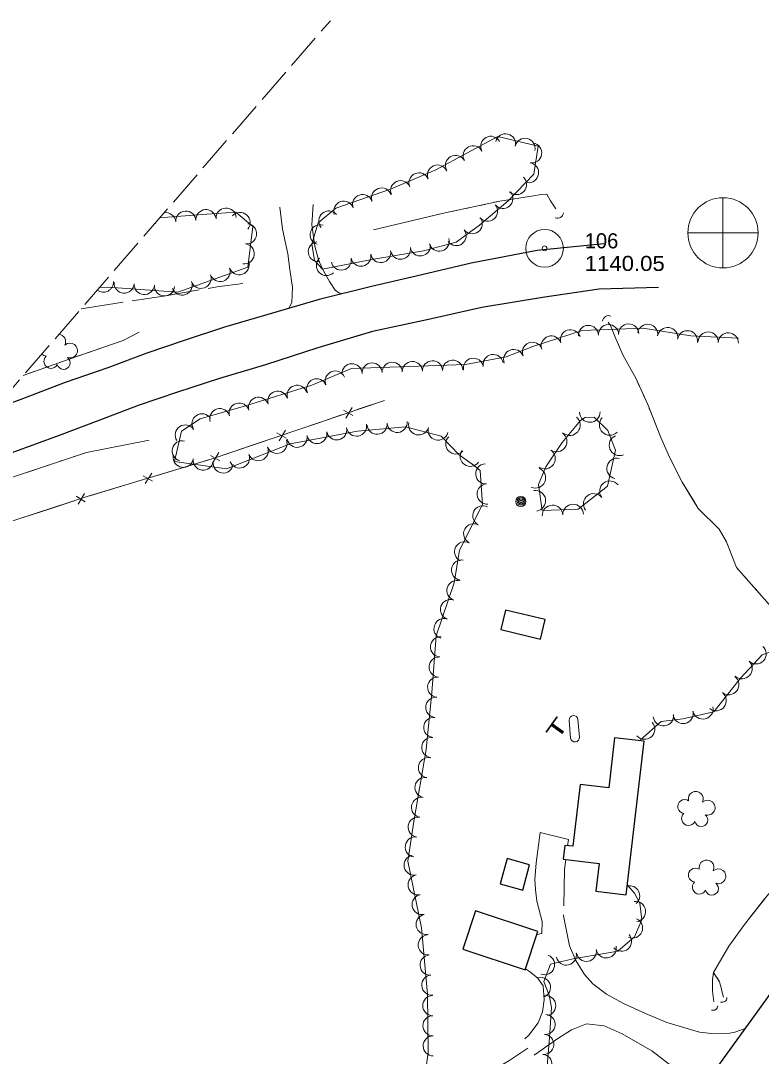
# Model space of a CAD drawing. Extents: x 297327 to 299792, y 46897 to 49095.
# Drawn here: x 298602.3 to 298897.4, y 48195.8 to 48608.4 of the extents above; entities that cross this region are included whole.
import ezdxf

# ---------------------------------------------------------------- set-up
doc = ezdxf.new("R2010")
doc.units = 0
doc.header["$LTSCALE"] = 2.4
doc.linetypes.add('LONG_DASHED', pattern=[7.5, 6, -1.5])
for name, color, linetype, lineweight in [('11', 7, 'Continuous', 25), ('12', 7, 'Continuous', 25), ('14', 7, 'Continuous', 13), ('15', 7, 'Continuous', 13), ('17', 7, 'LONG_DASHED', 13), ('18', 7, 'Continuous', 13), ('19', 7, 'Continuous', 13), ('4', 7, 'Continuous', 13), ('6', 7, 'Continuous', 13)]:
    doc.layers.add(name, color=color, linetype=linetype, lineweight=lineweight)

msp = doc.modelspace()

# ---------------------------------------------------------------- linework, layer by layer
at = {"layer": '11'}
for points in [[(298834.58, 48519.541), (298808.096, 48516.867), (298781.744, 48511.814), (298759.783, 48506.628), (298741.978, 48502.6), (298721.235, 48497.405), (298702.582, 48491.899), (298683.427, 48486.359), (298666.939, 48480.919), (298652.487, 48475.951), (298636.938, 48470.163), (298619.944, 48464.293), (298602.335, 48457.482), (298591.718, 48453.74)], [(298856.43, 48502.098), (298832.734, 48501.472), (298810.213, 48498.214), (298786.044, 48494.131), (298764.748, 48489.435), (298742.421, 48484.578), (298720.68, 48478.068), (298699.817, 48471.396), (298681.487, 48465.854), (298664.689, 48460.484), (298649.026, 48455.162), (298633.429, 48449.095), (298617.572, 48443.137), (298598.732, 48436.221), (298582.927, 48430.382), (298567.326, 48424.327), (298565.687, 48423.671)], [(298880.386, 48192.263), (298896.726, 48214.837), (298916.698, 48242.677), (298939.22, 48273.989), (298958.14, 48300.616), (298978.782, 48329.563), (298995.404, 48352.579), (299009.962, 48373.031)]]:
    msp.add_lwpolyline(points, dxfattribs=at)
at = {"layer": '12', "lineweight": 13}
for p, q in [((298820.803, 48329.684), (298821.393, 48322.612)), ((298824.869, 48322.998), (298824.29, 48329.997))]:
    msp.add_line(p, q, dxfattribs=at)
at = {"layer": '12'}
for points in [[(298793.634, 48365.84), (298809.373, 48362.075), (298811.225, 48369.819), (298795.486, 48373.584)], [(298843.528, 48260.207), (298850.668, 48321.348), (298838.877, 48322.725), (298836.552, 48302.815), (298825.14, 48304.148), (298822.261, 48279.497), (298819.076, 48279.869), (298818.431, 48274.347), (298832.728, 48272.678), (298831.437, 48261.619)], [(298802.291, 48262.047), (298805.064, 48272.11), (298796.09, 48274.583), (298793.317, 48264.52)], [(298808.358, 48245.517), (298783.494, 48253.777), (298778.445, 48238.58), (298803.309, 48230.32)]]:
    msp.add_lwpolyline(points, close=True, dxfattribs=at)
at = {"layer": '12', "lineweight": 13}
for centre, start, end in [((298822.548, 48329.829), 5.48716, 184.73785), ((298823.123, 48322.864), 188.30531, 4.35263)]:
    msp.add_arc(centre, 1.75, start, end, dxfattribs=at)
at = {"layer": '14'}
for centre, radius in [((298801.579, 48416.911), 2.018), ((298801.567, 48416.916), 1.518), ((298801.603, 48416.898), 1.008), ((298801.597, 48416.907), 0.502)]:
    msp.add_circle(centre, radius, dxfattribs=at)
at = {"layer": '15'}
for p, q in [((298736.38, 48453.477), (298747.155, 48457.128)), ((298730.897, 48453.211), (298734.581, 48451.095)), ((298731.78, 48450.073), (298734.273, 48454.355)), ((298709.862, 48444.493), (298720.638, 48448.143)), ((298720.638, 48448.143), (298730.115, 48451.354)), ((298704.38, 48444.227), (298708.064, 48442.11)), ((298705.263, 48441.089), (298707.756, 48445.37)), ((298694.121, 48439.159), (298703.598, 48442.37)), ((298678.745, 48432.104), (298681.239, 48436.386)), ((298683.345, 48435.508), (298694.121, 48439.159)), ((298667.485, 48430.543), (298677.064, 48433.435)), ((298677.863, 48435.242), (298681.547, 48433.125)), ((298651.106, 48427.172), (298654.717, 48424.933)), ((298651.883, 48424.006), (298654.518, 48428.202)), ((298656.594, 48427.254), (298667.485, 48430.543)), ((298640.683, 48422.45), (298650.262, 48425.342)), ((298624.301, 48418.975), (298627.96, 48416.815)), ((298625.147, 48415.827), (298627.691, 48420.079)), ((298629.791, 48419.161), (298640.683, 48422.45)), ((298613.983, 48414.029), (298623.497, 48417.128)), ((298603.165, 48410.505), (298613.983, 48414.029))]:
    msp.add_line(p, q, dxfattribs=at)
msp.add_lwpolyline([(298534.919, 48388.131), (298572.165, 48400.408), (298629.092, 48418.95), (298678.573, 48433.891), (298747.155, 48457.128)], dxfattribs=at)
for centre, radius, start, end in [((298816.143, 48532.11), 2.39, 249.05637, 355.29594), ((298836.548, 48488.525), 2.415, 68.75119, 174.99076), ((298881.729, 48219.281), 1.941, 252.37635, 358.61591), ((298878.133, 48216.081), 1.923, 250.35771, 356.59727)]:
    msp.add_arc(centre, radius, start, end, dxfattribs=at)
at = {"layer": '17'}
for points in [[(298718.843, 48535.226), (298718.267, 48527.067), (298719.41, 48518.552), (298721.025, 48512.769), (298723.001, 48508.553), (298725.242, 48504.475), (298727.613, 48501.024), (298728.973, 48499.987), (298730.374, 48499.694)], [(298709.091, 48493.82), (298710.252, 48496.273), (298710.522, 48502.085), (298709.443, 48509.294), (298708.649, 48515.534), (298706.605, 48525.35), (298705.509, 48534.221)], [(298626.278, 48493.66), (298628.89, 48494.087), (298659.171, 48498.686), (298680.575, 48502.417), (298690.747, 48503.678)], [(298807.993, 48244.42), (298808.096, 48244.39), (298809.864, 48244.804), (298810.02, 48249.57), (298807.896, 48257.678), (298807.383, 48262.345), (298807.191, 48266.302), (298807.606, 48272.895), (298809.248, 48284.994), (298820.539, 48282.233), (298820.21, 48279.737)], [(298819.482, 48274.224), (298818.954, 48270.219), (298818.565, 48251.79), (298820.941, 48239.787), (298823.517, 48234.002), (298826.854, 48228.436), (298830.262, 48224.688), (298835.676, 48220.546), (298842.423, 48216.931), (298851.184, 48212.896), (298859.734, 48209.26), (298872.738, 48205.465), (298878.777, 48204.832), (298884.865, 48205.046), (298886.836, 48205.469), (298890.964, 48206.876)], [(298803.158, 48202.748), (298804.786, 48204.215), (298808.492, 48209.226), (298810.226, 48213.551), (298810.85, 48218.323), (298810.469, 48223.937), (298808.179, 48227.132), (298805.034, 48229.683), (298803.441, 48230.718)], [(298869.073, 48176.256), (298867.134, 48182.115), (298864.799, 48187.957), (298861.825, 48191.745), (298853.755, 48197.965), (298841.935, 48204.811), (298834.747, 48207.957), (298827.75, 48208.774), (298821.748, 48206.38), (298816.292, 48202.905), (298806.831, 48196.299)], [(298804.335, 48199.125), (298796.758, 48194.022), (298786.781, 48188.133), (298778.292, 48181.845), (298770.455, 48177.553)]]:
    msp.add_lwpolyline(points, dxfattribs=at)
at = {"layer": '18'}
for points in [[(298742.14, 48513.345), (298762.786, 48516.799), (298775.799, 48520.228), (298785.011, 48527.03), (298796.527, 48536.684), (298806.662, 48547.28), (298808.462, 48558.512), (298792.349, 48562.291), (298767.711, 48548.989), (298749.634, 48541.295), (298727.813, 48533.698), (298720.821, 48527.878), (298718.241, 48519.517), (298719.276, 48512.914), (298722.571, 48509.453)], [(298825.369, 48449.109), (298827.153, 48450.341), (298830.768, 48450.447), (298836.171, 48445.153), (298839.328, 48437.339), (298836.121, 48422.963), (298824.458, 48413.893), (298810.059, 48413.347), (298808.528, 48423.725), (298811.512, 48430.724), (298818.079, 48440.336)]]:
    msp.add_lwpolyline(points, close=True, dxfattribs=at)
for points in [[(298633.6, 48502.117), (298637.148, 48502.284), (298664.884, 48500.296), (298692.743, 48510.207), (298694.729, 48526.463), (298688.014, 48532.202), (298676.392, 48531.314), (298659.191, 48530.022), (298657.639, 48529.885)], [(298888.333, 48482.021), (298869.25, 48482.856), (298850.261, 48485.928), (298825.993, 48485.069), (298806.332, 48478.653), (298795.721, 48474.584), (298779.544, 48471.5), (298760.873, 48470.845), (298734.01, 48469.876), (298718.26, 48463.222), (298691.855, 48455.025), (298673.708, 48449.832), (298666.266, 48444.895), (298663.509, 48432.876), (298684.203, 48429.907), (298709.568, 48439.811), (298736.457, 48444.85), (298755.575, 48446.597), (298769.742, 48442.882), (298776.92, 48435.465), (298783.096, 48431.086), (298785.387, 48429.241), (298786.297, 48415.628), (298777.106, 48397.513), (298774.928, 48384.49), (298767.755, 48363.384), (298766.143, 48340.734), (298763.87, 48318.109), (298758.853, 48289.38), (298756.556, 48273.526), (298761.957, 48247.037), (298764.304, 48220.602), (298764.559, 48197.242), (298760.904, 48170.711)], [(298849.244, 48321.907), (298857.535, 48329.28), (298866.122, 48330.268), (298878.495, 48333.027), (298889.123, 48346.539), (298897.753, 48355.771), (298909.657, 48359.901), (298911.987, 48373.993), (298905.69, 48386.836), (298907.189, 48404.412), (298912.175, 48421.888), (298921.692, 48430.031), (298932.836, 48431.368), (298939.927, 48433.501)], [(298811.357, 48183.936), (298812.99, 48203.324), (298813.738, 48215.23), (298812.856, 48220.207), (298810.703, 48225.665), (298813.349, 48232.565), (298822.405, 48234.64), (298840.23, 48237.68), (298846.81, 48243.389), (298849.776, 48250.21), (298848.936, 48256.882), (298846.808, 48260.777), (298843.956, 48264.201)]]:
    msp.add_lwpolyline(points, dxfattribs=at)
for centre, radius, start, end in [((298795.467, 48559.414), 3.991, 346.80857, 166.79325), ((298789.568, 48558.416), 3.991, 28.37217, 208.35685), ((298803.238, 48557.592), 3.991, 346.80857, 166.79325), ((298805.908, 48555.777), 3.991, 260.90306, 80.88774), ((298782.545, 48554.624), 3.991, 28.37217, 208.35685), ((298768.316, 48546.976), 3.991, 23.06342, 203.04809), ((298775.522, 48550.832), 3.991, 28.37217, 208.35685), ((298804.645, 48547.896), 3.991, 260.90306, 80.88774), ((298760.972, 48543.851), 3.991, 23.06342, 203.04809), ((298753.628, 48540.725), 3.991, 23.06342, 203.04809), ((298799.836, 48543.166), 3.991, 226.28155, 46.26623), ((298738.506, 48535.209), 3.991, 19.20327, 199.18794), ((298746.044, 48537.833), 3.991, 19.20327, 199.18794), ((298794.411, 48537.636), 3.991, 219.98117, 39.96584), ((298730.969, 48532.585), 3.991, 19.20327, 199.18794), ((298788.295, 48532.509), 3.991, 219.98117, 39.96584), ((298660.022, 48527.972), 4.025, 4.30319, 98.4609), ((298668.048, 48528.575), 4.025, 4.30319, 184.28787), ((298676.074, 48529.178), 4.025, 4.30319, 184.28787), ((298684.102, 48529.79), 4.025, 4.37696, 184.36164), ((298689.659, 48528.025), 4.025, 319.48868, 139.47336), ((298725.025, 48528.659), 3.991, 39.78098, 219.76566), ((298652.031, 48527.275), 4.025, 5.05662, 10.14382), ((298660.022, 48527.972), 4.025, 179.77176, 184.28787), ((298692.252, 48523.562), 4.025, 263.04234, 83.02701), ((298721.564, 48523.201), 3.991, 72.85872, 252.84339), ((298782.206, 48527.555), 3.991, 216.44926, 36.43393), ((298775.785, 48522.814), 3.991, 216.44926, 36.43393), ((298691.276, 48515.573), 4.025, 263.04234, 83.02701), ((298720.844, 48516.401), 3.991, 98.91611, 278.90079), ((298753.603, 48517.381), 3.991, 189.50508, 9.48976), ((298761.475, 48518.698), 3.991, 189.50508, 9.48976), ((298769.024, 48520.603), 3.991, 194.76986, 14.75454), ((298724.084, 48510.893), 3.991, 133.60014, 313.58482), ((298729.991, 48513.059), 3.991, 191.25621, 11.24089), ((298737.819, 48514.615), 3.991, 191.25621, 11.24089), ((298745.732, 48516.064), 3.991, 189.50508, 9.48976), ((298681.722, 48508.522), 4.025, 199.59097, 19.57565), ((298689.305, 48511.22), 4.025, 199.59097, 19.57565), ((298674.139, 48505.824), 4.025, 199.59097, 19.57565), ((298635.187, 48504.301), 4.025, 232.3778, 2.68633), ((298643.468, 48503.943), 4.025, 175.90795, 355.89263), ((298651.496, 48503.368), 4.025, 175.90795, 355.89263), ((298659.524, 48502.792), 4.025, 175.90795, 355.89263), ((298666.556, 48503.127), 4.025, 199.59097, 19.57565), ((298821.311, 48481.331), 4.014, 18.08079, 198.06547), ((298828.483, 48483.055), 4.014, 2.03488, 182.01956), ((298836.505, 48483.339), 4.014, 2.03488, 182.01956), ((298844.527, 48483.623), 4.014, 2.03488, 182.01956), ((298852.112, 48483.5), 4.014, 350.81809, 170.80277), ((298860.036, 48482.218), 4.014, 350.81809, 170.80277), ((298867.96, 48480.937), 4.014, 350.81809, 170.80277), ((298617.18, 48480.536), 2.974, 332.83167, 84.23449), ((298813.68, 48478.841), 4.014, 18.08079, 198.06547), ((298876.212, 48480.448), 4.014, 357.50221, 177.48689), ((298884.231, 48480.098), 4.014, 357.50221, 177.48689), ((298612.734, 48477.517), 2.777, 55.80256, 55.86202), ((298617.18, 48480.536), 2.974, 193.99816, 194.06555), ((298621.875, 48477.04), 2.975, 250.48248, 133.45575), ((298798.671, 48473.465), 4.014, 20.98798, 200.97266), ((298806.166, 48476.339), 4.014, 20.98798, 200.97266), ((298612.734, 48477.517), 2.777, 222.37064, 263.57555), ((298614.303, 48472.705), 2.783, 132.47957, 333.49062), ((298619.314, 48472.147), 2.611, 195.18772, 53.12032), ((298758.32, 48468.651), 4.014, 2.07354, 182.05821), ((298766.34, 48468.935), 4.014, 2.01684, 182.00152), ((298774.362, 48469.216), 4.014, 2.01684, 182.00152), ((298782.657, 48469.955), 4.014, 10.80107, 190.78575), ((298790.542, 48471.458), 4.014, 10.80107, 190.78575), ((298727.589, 48464.883), 4.014, 22.91056, 202.89524), ((298734.254, 48467.783), 4.014, 2.07354, 182.05821), ((298742.276, 48468.072), 4.014, 2.07354, 182.05821), ((298750.298, 48468.361), 4.014, 2.07354, 182.05821), ((298720.195, 48461.759), 4.014, 22.91056, 202.89524), ((298704.709, 48456.815), 4.014, 17.25376, 197.23844), ((298712.375, 48459.195), 4.014, 17.25376, 197.23844), ((298689.311, 48452.112), 4.014, 15.97683, 195.9615), ((298697.042, 48454.436), 4.014, 17.25376, 197.23844), ((298674.514, 48447.846), 4.014, 33.56784, 213.55251), ((298681.593, 48449.903), 4.014, 15.97683, 195.9615), ((298829.031, 48452.548), 4.11, 181.68722, 1.6719), ((298744.256, 48447.672), 4.014, 185.22884, 5.21352), ((298752.25, 48448.403), 4.014, 185.22884, 5.21352), ((298760.829, 48447.391), 4.014, 165.31388, 345.29856), ((298821.089, 48447.324), 4.11, 230.28248, 50.26716), ((298836.947, 48447.404), 4.11, 135.59147, 315.57615), ((298667.825, 48443.408), 4.014, 33.56784, 213.55251), ((298720.287, 48443.957), 4.014, 190.62179, 10.60646), ((298728.177, 48445.436), 4.014, 190.62179, 10.60646), ((298736.067, 48446.914), 4.014, 190.62179, 10.60646), ((298768.593, 48445.355), 4.014, 165.31388, 345.29856), ((298815.784, 48440.79), 4.11, 235.66644, 55.65112), ((298666.626, 48437.066), 4.014, 77.08827, 257.07295), ((298704.375, 48440.039), 4.014, 201.33628, 21.32096), ((298712.398, 48442.479), 4.014, 190.62179, 10.60646), ((298775.625, 48439.824), 4.014, 134.0695, 314.05418), ((298840.861, 48439.286), 4.11, 112.00728, 291.99196), ((298689.42, 48434.2), 4.014, 201.33628, 21.32096), ((298696.898, 48437.119), 4.014, 201.33628, 21.32096), ((298781.393, 48434.869), 4.014, 144.66969, 324.65436), ((298811.148, 48434.004), 4.11, 235.66644, 55.65112), ((298667.02, 48434.495), 4.014, 171.84306, 351.82774), ((298674.966, 48433.355), 4.014, 171.84306, 351.82774), ((298682.912, 48432.215), 4.014, 171.84306, 351.82774), ((298787.584, 48427.876), 4.014, 93.83207, 273.81675), ((298839.906, 48430.051), 4.11, 77.43202, 257.4167), ((298807.292, 48426.31), 4.11, 246.91685, 66.90153), ((298788.119, 48419.867), 4.014, 93.83207, 273.81675), ((298837.065, 48420.973), 4.11, 37.8789, 217.86358), ((298807.323, 48417.154), 4.11, 278.39961, 98.38429), ((298830.578, 48415.928), 4.11, 37.8789, 217.86358), ((298786.397, 48411.182), 4.014, 63.10581, 243.09049), ((298814.191, 48411.351), 4.11, 2.17924, 182.16391), ((298822.403, 48411.663), 4.11, 2.17924, 182.16391), ((298782.765, 48404.024), 4.014, 63.10581, 243.09049), ((298779.133, 48396.865), 4.014, 63.10581, 243.09049), ((298777.91, 48389.584), 4.014, 80.51324, 260.49791), ((298776.109, 48381.437), 4.014, 71.23703, 251.2217), ((298773.526, 48373.837), 4.014, 71.23703, 251.2217), ((298770.943, 48366.237), 4.014, 71.23703, 251.2217), ((298769.545, 48358.945), 4.014, 85.93679, 265.92146), ((298895.254, 48356.208), 4.058, 226.93796, 46.92264), ((298768.975, 48350.939), 4.014, 85.93679, 265.92146), ((298889.713, 48350.28), 4.058, 226.93796, 46.92264), ((298768.406, 48342.932), 4.014, 85.93679, 265.92146), ((298884.376, 48343.939), 4.058, 231.82048, 51.80516), ((298879.36, 48337.562), 4.058, 231.82048, 51.80516), ((298767.666, 48334.878), 4.014, 84.27074, 264.25542), ((298866.194, 48332.46), 4.058, 192.57814, 12.56282), ((298874.114, 48334.226), 4.058, 192.57814, 12.56282), ((298766.864, 48326.891), 4.014, 84.27074, 264.25542), ((298850.865, 48326.19), 4.058, 221.65364, 41.63832), ((298858.362, 48331.513), 4.058, 186.57112, 6.55579), ((298766.061, 48318.904), 4.014, 84.27074, 264.25542), ((298764.733, 48310.836), 4.014, 80.10188, 260.08656), ((298763.352, 48302.928), 4.014, 80.10188, 260.08656), ((298871.286, 48298.408), 2.974, 332.83167, 194.06555), ((298761.971, 48295.021), 4.014, 80.10188, 260.08656), ((298866.84, 48295.389), 2.777, 55.80256, 263.57555), ((298875.981, 48294.912), 2.975, 250.48248, 133.45575), ((298760.655, 48287.165), 4.014, 81.76375, 261.74843), ((298868.409, 48290.577), 2.783, 132.47957, 333.49062), ((298873.42, 48290.019), 2.611, 195.18772, 53.12032), ((298759.504, 48279.221), 4.014, 81.76375, 261.74843), ((298759.008, 48272.017), 4.014, 101.53207, 281.51675), ((298871.116, 48268.049), 2.777, 55.80256, 263.57555), ((298875.562, 48271.068), 2.974, 332.83167, 194.06555), ((298880.257, 48267.572), 2.975, 250.48248, 133.45575), ((298760.612, 48264.151), 4.014, 101.53207, 281.51675), ((298844.91, 48259.773), 4.014, 309.80006, 104.10452), ((298872.685, 48263.237), 2.783, 132.47957, 333.49062), ((298877.696, 48262.679), 2.611, 195.18772, 53.12032), ((298762.215, 48256.286), 4.014, 101.53207, 281.51675), ((298847.244, 48253.499), 4.014, 277.18341, 97.16808), ((298763.819, 48248.421), 4.014, 101.53207, 281.51675), ((298846.076, 48246.969), 4.014, 246.50664, 66.49132), ((298764.673, 48240.207), 4.014, 95.0813, 275.06597), ((298841.629, 48241.675), 4.014, 220.95352, 40.9382), ((298827.673, 48237.67), 4.014, 189.68616, 9.67084), ((298835.586, 48239.019), 4.014, 189.68616, 9.67084), ((298765.382, 48232.212), 4.014, 95.0813, 275.06597), ((298811.008, 48232.327), 4.014, 249.02693, 69.01161), ((298819.67, 48236.169), 4.014, 192.91307, 12.89774), ((298766.092, 48224.216), 4.014, 95.0813, 275.06597), ((298809.372, 48223.314), 4.014, 291.53525, 111.51993), ((298766.455, 48216.04), 4.014, 90.63308, 270.61776), ((298811.461, 48216.042), 4.014, 280.05701, 100.04169), ((298811.213, 48208.545), 4.014, 266.41275, 86.39743), ((298766.542, 48208.013), 4.014, 90.63308, 270.61776), ((298810.651, 48200.583), 4.014, 265.19315, 85.17783), ((298766.63, 48199.987), 4.014, 90.63308, 270.61776), ((298809.977, 48192.584), 4.014, 265.19315, 85.17783)]:
    msp.add_arc(centre, radius, start, end, dxfattribs=at)
at = {"layer": '19'}
for p, q in [((298785.318, 48534.871), (298787.212, 48535.28)), ((298742.824, 48525.177), (298770.17, 48531.597)), ((298773.956, 48532.423), (298775.849, 48532.831)), ((298779.637, 48533.647), (298781.531, 48534.055)), ((298616.987, 48472.004), (298618.856, 48472.678)), ((298605.771, 48467.959), (298607.64, 48468.633)), ((298611.379, 48469.982), (298613.248, 48470.656)), ((298851.17, 48457.593), (298850.357, 48459.372)), ((298853.445, 48452.189), (298852.719, 48454.005)), ((298855.622, 48446.743), (298854.896, 48448.558)), ((298611.708, 48430.849), (298613.449, 48431.426)), ((298616.931, 48432.581), (298618.672, 48433.158)), ((298622.153, 48434.312), (298623.894, 48434.889)), ((298892.2, 48385.274), (298890.916, 48386.749)), ((298896.057, 48380.856), (298894.769, 48382.326)), ((298878.272, 48228.464), (298878.35, 48229.02)), ((298878.037, 48226.794), (298878.115, 48227.35)), ((298878.852, 48228.502), (298879.149, 48228.025))]:
    msp.add_line(p, q, dxfattribs=at)
for points in [[(298742.824, 48525.177), (298770.696, 48531.72), (298793.153, 48536.56), (298806.61, 48538.682), (298809.664, 48539.141), (298811.934, 48539.27), (298813.338, 48536.672), (298815.544, 48533.553)], [(298791, 48536.096), (298793.153, 48536.56), (298806.61, 48538.682), (298809.664, 48539.141), (298811.934, 48539.27), (298813.338, 48536.672), (298815.544, 48533.553)], [(298911.507, 48273.843), (298914.609, 48293.775), (298911.084, 48316.942), (298908.451, 48339.55), (298905.863, 48357.417), (298901.52, 48374.62), (298894.442, 48382.699), (298887.513, 48390.656), (298883.466, 48400.762), (298880.607, 48405.88), (298872.229, 48414.032), (298865.894, 48424.534), (298860.761, 48434.598), (298857.367, 48442.376), (298852.093, 48455.572), (298847.442, 48465.754), (298842.16, 48475.328), (298839.187, 48482.326), (298837.213, 48487.053), (298836.315, 48488.339)], [(298848.733, 48462.928), (298847.442, 48465.754), (298842.16, 48475.328), (298839.187, 48482.326), (298837.213, 48487.053), (298836.315, 48488.339)], [(298603.237, 48467.045), (298621.533, 48473.644), (298643.137, 48481.01), (298649.414, 48484.383)], [(298622.601, 48474.008), (298643.137, 48481.01), (298649.414, 48484.383)], [(298554.093, 48410.278), (298567.964, 48416.482), (298601.437, 48427.444), (298628.463, 48436.404), (298653.444, 48441.348)], [(298627.376, 48436.044), (298628.463, 48436.404), (298653.444, 48441.348)], [(298869.902, 48417.889), (298865.894, 48424.534), (298860.761, 48434.598), (298857.367, 48442.376), (298857.073, 48443.112)], [(298582.977, 48421.399), (298601.437, 48427.444), (298608.226, 48429.695)], [(298885.805, 48394.922), (298883.466, 48400.762), (298880.607, 48405.88), (298872.229, 48414.032), (298869.902, 48417.889)], [(298888.348, 48389.698), (298887.513, 48390.656), (298887.259, 48391.291)], [(298878.383, 48229.255), (298884.484, 48239.773), (298890.633, 48248.377), (298899.59, 48259.658), (298911.507, 48273.843), (298920.17, 48280.279), (298928.495, 48288.556), (298938.783, 48300.785), (298950.348, 48316.747), (298963.7, 48334.694), (298978.43, 48354.318), (298991.544, 48372.761), (298999.485, 48383.835)], [(298878.383, 48229.255), (298884.484, 48239.773), (298890.633, 48248.377), (298898.695, 48258.53)], [(298878.393, 48217.558), (298877.859, 48221.734), (298877.99, 48226.463), (298878.383, 48229.255), (298880.721, 48225.502), (298881.574, 48222.603), (298881.81, 48221.252), (298882.373, 48219.43)], [(298878.393, 48217.558), (298877.859, 48221.734), (298877.968, 48225.673)], [(298879.744, 48227.07), (298880.721, 48225.502), (298881.574, 48222.603), (298881.81, 48221.252), (298882.373, 48219.43)]]:
    msp.add_lwpolyline(points, dxfattribs=at)
at = {"layer": '4', "linetype": 'LONG_DASHED'}
msp.add_line((298026.893, 47801.312), (298725.651, 48608.445), dxfattribs=at)
at = {"layer": '4'}
for p, q in [((298882.053, 48537.953), (298881.988, 48510.099)), ((298868.144, 48523.923), (298896.049, 48523.91))]:
    msp.add_line(p, q, dxfattribs=at)
msp.add_circle((298882.105, 48523.931), 14, dxfattribs=at)
at = {"layer": '6'}
for radius in [7.5, 0.96]:
    msp.add_circle((298811.001, 48517.751), radius, dxfattribs=at)

# ---------------------------------------------------------------- texts
at = {"layer": '12', "width": 1.7}
msp.add_text('T', height=6, rotation=54.408, dxfattribs=at).set_placement((298816.011, 48321.354))
at = {"layer": '6'}
msp.add_text('106', height=6, dxfattribs=at).set_placement((298827.001, 48517.751))
at = {"layer": '6', "width": 1.1}
msp.add_text('1140.05', height=6, dxfattribs=at).set_placement((298827.001, 48508.751))

doc.saveas('drawing.dxf')
